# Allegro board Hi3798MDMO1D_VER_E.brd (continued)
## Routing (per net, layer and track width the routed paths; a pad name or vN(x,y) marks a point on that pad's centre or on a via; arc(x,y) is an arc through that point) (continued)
DDR_ADDR3: length 127.3
  TOP w0.127: U21.K2 37.09,12.08 38.2,12.08 39.04,11.24 39.04,8.37 v2(39.11,8.3) ; U3.K2 35.31,46.38 35.31,45.56 34.31,44.56 31.75,44.56 v2(31.57,44.38) ; U6.K2 35.31,31.75 35.31,30.79 34.44,29.93 32.2,29.93 30.8,28.53 v2(30.8,27.96) ; U20.K2 52.22,12.08 53.15,12.08 54.07,11.17 54.07,8.48 v2(54.2,8.35) 54.72,7.83 54.72,7.34 56.3,5.76 57.13,5.76 63.31,11.93 63.31,21.85 60.51,24.65 60.51,27.68 59.92,28.27 U1.AC14
  BOTTOM w0.127: RN6.2 29.95,47.17 30.56,46.55 30.56,46.35 31.57,45.34 v2(31.57,44.38) 31.57,43.75 31.06,43.24 31.06,42.12 30.16,41.22 30.16,32.18 31.53,30.81 31.53,28.44 31.04,27.96 v2(30.8,27.96) 30.8,27.96 30.7,27.96 25.82,23.07 25.82,12.98 31.59,7.21 37.58,7.21 38.67,8.3 v2(39.11,8.3) 39.52,7.89 41.14,7.89 41.64,7.39 47.3,7.39 47.66,7.03 51.44,7.03 52.76,8.35 v2(54.2,8.35)
DDR_ADDR4: length 105
  TOP w0.127: v2(41.88,11.29) U21.L8 ; U6.L8 34.92,27.36 v2(34.52,26.96) ; U1.W12 v2(57.92,31.8) ; U20.L8 v2(57.01,12.09) ; U3.L8 34.92,41.99 v2(34.52,41.59)
  BOTTOM w0.127: RN4.3 32.11,48.28 34.55,45.85 34.55,42.96 34.92,42.59 34.92,41.99 v2(34.52,41.59) 34.52,41.37 33.96,40.81 33.51,40.81 32.75,40.05 32.75,39.62 32.88,39.49 32.88,34.66 33.72,33.82 33.72,33.42 34.55,32.59 34.55,28.35 34.91,27.99 34.91,27.6 34.52,27.2 v2(34.52,26.96) 34.52,26.52 33.71,25.71 33.71,25.6 33.43,25.32 32.01,25.32 28.48,21.79 28.48,14.09 32.67,9.9 34.71,9.9 34.91,9.7 35.79,9.7 37.39,11.29 40.46,11.29 40.85,11.68 41.48,11.68 v2(41.88,11.29) 42.3,11.29 43.09,10.49 43.55,10.49 43.91,10.13 49.3,10.13 49.77,9.67 50.65,9.67 52.3,11.32 55.63,11.32 56.01,11.7 56.62,11.7 v2(57.01,12.09) 57.82,11.28 59.54,11.28 60.6,12.35 60.6,20.15 57.55,23.2 57.55,29.02 57.44,29.13 57.44,30.53 57.92,31.01 v2(57.92,31.8)
DDR_ADDR5: length 132.1
  TOP w0.127: v1(39.91,6.9) 39.3,6.9 38.41,7.79 38.41,10.72 38.2,10.93 38.2,10.94 37.82,11.32 37.29,11.32 36.91,11.69 U21.L2 ; U6.L2 34.92,31.92 34.55,31.55 34.55,31.02 34.01,30.49 32.12,30.49 32.11,30.48 31.57,30.48 30.54,29.44 v2(30.54,28.92) ; v1(55.43,5.79) 55.1,6.12 54.52,6.12 53.81,6.83 53.81,7.56 53.51,7.86 53.51,10.73 52.92,11.32 52.42,11.32 52.05,11.69 U20.L2 ; U1.Y15 v2(61.12,31) ; v2(30.61,44.43) 31.34,45.17 34.06,45.17 34.55,45.65 34.55,46.14 34.92,46.51 U3.L2
  BOTTOM w0.127: v2(61.12,31) 61.96,30.16 61.96,28.24 62.3,27.9 62.3,24.2 64.44,22.06 64.44,10.79 59.43,5.79 v1(55.43,5.79) 55.33,5.89 54.03,5.89 53.17,5.02 45.6,5.02 44.04,6.59 40.41,6.59 40.09,6.9 v1(39.91,6.9) 38.64,6.9 38.18,6.45 31.27,6.45 25.05,12.67 25.05,23.41 30.54,28.9 v2(30.54,28.92) 30.54,29.36 30.54,29.37 30.54,30.17 29.4,31.32 29.4,41.68 30.29,42.57 30.29,44.11 v2(30.61,44.43) 30.61,45.42 29.87,46.16 RN6.4
DDR_ADDR6: length 104.3
  TOP w0.127: v2(33.72,26.96) 34.12,27.36 U6.M8 ; v2(41.88,10.49) U21.M8 ; v2(33.72,41.59) 34.12,41.99 U3.M8 ; U20.M8 v2(57.01,10.49) 59.3,10.49 61.76,12.95 61.76,21.25 58.89,24.12 58.89,26.41 56.8,28.49 56.8,29.38 57.08,29.66 57.08,30.24 U1.AA10
  BOTTOM w0.127: v2(57.01,10.49) 52.46,10.49 50.99,9.01 49.06,9.01 48.79,9.28 42.78,9.28 42.27,9.79 42.27,10.1 v2(41.88,10.49) 37.78,10.49 36.41,9.11 32.38,9.11 27.72,13.77 27.72,22.15 31.55,25.98 32.38,25.98 32.78,26.39 33.14,26.39 v2(33.72,26.96) 33.72,31.95 32.06,33.6 32.06,40.18 33.47,41.59 v2(33.72,41.59) 33.72,45.61 31.4,47.93 31.4,49.07 30.36,50.11 RN3.1
DDR_ADDR7: length 116.1
  TOP w0.127: RN2.2 33.64,50.14 33.84,49.93 33.84,49.31 33.72,49.19 33.72,47.51 34.12,47.11 U3.M2 34.12,46.6 33.74,46.22 33.74,45.81 33.57,45.65 30.75,45.65 29.78,44.67 29.78,44.01 30.36,43.43 30.36,43.12 30.79,42.69 30.79,36.98 33.72,34.05 33.72,32.86 34.12,32.46 U6.M2 34.12,31.97 33.71,31.56 33.71,31.19 33.54,31.02 31.11,31.02 29.75,29.66 29.75,24.58 31.07,23.26 31.07,15.49 33.82,12.75 33.82,11.98 34.53,11.27 34.53,10.97 35.01,10.49 36.06,10.49 36.46,10.89 U21.M2 36.89,10.89 37.35,10.43 37.62,10.43 37.83,10.22 37.83,9.9 37.63,9.7 37.63,7.44 38.92,6.14 42.71,6.14 44.03,4.82 47.35,4.82 48.68,6.14 48.68,8.17 49.79,9.29 49.79,10.21 50.08,10.5 51.15,10.5 51.54,10.89 U20.M2 51.98,10.89 52.38,10.49 52.79,10.49 52.99,10.28 52.99,9.77 52.74,9.52 52.74,7.59 53.09,7.23 53.09,6.37 54.59,4.87 56.8,4.87 63.69,11.76 63.69,22.02 60.92,24.79 60.92,27.94 60.36,28.49 60.36,29.36 U1.AB14
DDR_ADDR8: length 103.7
  TOP w0.127: v2(32.92,41.59) U3.N8 ; v2(32.92,26.96) U6.N8 ; U20.N8 v2(57.01,9.69) 59.18,9.69 62.14,12.64 62.14,21.41 59.32,24.22 59.32,26.61 57.16,28.77 57.16,29.23 57.52,29.59 U1.AB11 ; v2(41.88,9.69) U21.N8
  BOTTOM w0.127: v2(57.01,9.69) 56.62,10.08 52.54,10.08 51.14,8.68 48.68,8.68 48.46,8.9 42.67,8.9 v2(41.88,9.69) 41.48,10.08 38.06,10.08 36.71,8.73 32.22,8.73 27.34,13.61 27.34,22.33 31.32,26.31 32.14,26.31 32.79,26.96 v2(32.92,26.96) 33.31,27.36 33.31,31.64 31.68,33.27 31.68,40.41 32.87,41.59 v2(32.92,41.59) 33.31,41.99 33.31,45.51 31.02,47.8 31.02,48.81 30.23,49.6 RN3.2
DDR_ADDR9: length 118.4
  TOP w0.127: U1.Y16 v2(61.92,31.8) ; RN2.3 34.15,50.21 34.51,49.85 34.51,46.56 34.12,46.17 U3.M3 34.12,45.74 33.8,45.42 31.01,45.42 30.16,44.57 30.16,44.12 30.74,43.53 30.74,43.28 31.2,42.82 31.2,37.26 34.52,33.93 34.52,31.97 34.12,31.56 U6.M3 34.12,31.11 33.77,30.76 31.34,30.76 30.13,29.56 30.13,24.81 31.45,23.49 31.45,17.06 33.42,15.1 33.42,13.7 34.17,12.95 34.17,12.21 35.09,11.3 36.93,11.3 37.33,10.89 U21.M3 37.69,10.89 38.11,10.47 38.11,9.67 38.01,9.57 38.01,7.62 39.15,6.48 43.01,6.48 44.26,5.23 47.13,5.23 48.28,6.38 48.28,8.41 49.36,9.5 49.36,10.64 50.02,11.3 52.03,11.3 52.44,10.89 U20.M3 52.84,10.89 53.25,10.48 53.25,9.6 53.12,9.47 53.12,7.72 53.42,7.41 53.42,6.62 54.62,5.43 v1(54.69,5.43)
  BOTTOM w0.127: v1(54.69,5.43) 54.82,5.3 59.49,5.3 64.82,10.63 64.82,22.22 62.68,24.36 62.68,28.31 62.31,28.67 62.31,31.4 v2(61.92,31.8)
DDR_ADDR10: length 93.6
  TOP w0.127: v2(36.89,28.67) 37.32,28.24 U6.H7 ; v2(55.36,13.56) 55.36,13.63 U20.H7 ; U3.H7 37.32,42.9 36.99,43.23 v2(36.84,43.23) ; 55.12,31.4 55.12,31.38 54.72,30.98 v2(54.72,29.4) ; U21.H7 40.6,14.09 v2(40.24,13.73)
  BOTTOM w0.127: v2(54.72,29.4) 54.72,23.59 56.14,22.17 56.14,19.76 57.51,18.39 57.51,16.35 58.28,15.58 58.28,14.3 58.08,14.09 57.79,14.09 57.57,13.86 55.66,13.86 v2(55.36,13.56) 55.03,13.24 52.71,13.24 52.26,13.68 50.2,13.68 50.02,13.51 46.39,13.51 45.81,14.08 40.59,14.08 v2(40.24,13.73) 40.24,13.51 39.97,13.24 35.9,13.24 35.45,13.68 32.66,13.68 30.41,15.93 30.41,20.96 32.36,22.91 35.94,22.91 37.31,24.28 37.31,28.25 v2(36.89,28.67) 36.53,29.03 36.53,32.34 37.31,33.12 37.31,33.94 36.91,34.34 36.91,41 37.04,41.12 37.04,42.39 37.14,42.48 37.14,42.93 v2(36.84,43.23) 36.53,43.54 36.53,47.24 36.13,47.65 36.13,47.99 36.12,47.99 36.12,48.32 36.13,48.33 36.13,49.6 36.13,49.61 36.13,50.42 35.51,51.05 RN7.1
DDR_ADDR11: length 103.3
  TOP w0.127: v2(41.08,11.29) U21.M7 ; v2(34.52,27.76) U6.M7 ; U1.AB9 56.42,29.3 56.42,28.24 58.46,26.21 58.46,24.01 61.38,21.09 61.38,13.23 59.44,11.29 v2(56.21,11.29) U20.M7 ; v2(34.52,42.39) U3.M7
  BOTTOM w0.127: RN4.4 31.61,49.5 31.76,49.35 31.76,48.08 34.16,45.67 34.16,42.74 v2(34.52,42.39) 34.12,42 34.12,41.44 33.77,41.09 33.38,41.09 32.42,40.13 32.42,33.9 34.12,32.2 34.12,28.16 v2(34.52,27.76) 34.12,27.37 34.12,26.81 33.47,26.16 33.13,26.16 32.57,25.6 31.73,25.6 28.1,21.97 28.1,13.93 32.54,9.5 33.72,9.5 33.75,9.47 36.18,9.47 37.6,10.89 40.67,10.89 v2(41.08,11.29) 41.48,10.88 42.04,10.88 42.5,10.42 42.5,10.16 42.99,9.67 49.06,9.67 49.39,9.34 50.81,9.34 52.4,10.94 55.86,10.94 v2(56.21,11.29)
DDR_ADDR12: length 98.3
  TOP w0.127: v2(36.12,27.76) U6.K7 ; v2(56.21,12.89) U20.K7 ; v2(41.08,12.89) U21.K7 ; v2(36.12,42.39) U3.K7 ; U1.Y10 v2(56.32,31)
  BOTTOM w0.127: RN7.4 33.99,50.65 34.52,50.11 34.52,47.65 35.69,46.49 35.69,42.97 36.12,42.54 36.12,42.39 v2(36.12,42.39) 36.52,41.99 36.52,41.33 36.1,40.91 35.75,40.91 35.32,40.49 35.32,37.53 36.12,36.73 36.12,33.33 35.69,32.9 35.69,28.4 36.12,27.97 v2(36.12,27.76) 36.51,27.37 36.51,24.58 35.6,23.67 32.01,23.67 29.64,21.31 29.64,15.03 32.82,11.86 34.81,11.86 35.04,12.09 35.4,12.09 35.79,12.49 40.49,12.49 40.89,12.89 v2(41.08,12.89) 41.54,13.35 42.14,13.35 42.6,12.88 45.74,12.88 46.52,12.11 50.16,12.11 50.18,12.1 50.5,12.1 50.52,12.11 50.61,12.11 50.96,12.46 55.58,12.46 56.01,12.89 v2(56.21,12.89) 56.61,13.28 57.36,13.28 57.69,12.95 58.2,12.95 59.83,14.58 59.83,19.72 56.71,22.84 56.71,30.6 v2(56.32,31)
DDR_ADDR13: length 118.8
  TOP w0.127: RN2.1 33.13,50.22 32.89,49.99 32.89,47.48 33.12,47.25 33.48,47.25 33.66,47.07 33.66,46.57 33.32,46.22 U3.N3 30.54,45.99 29.37,44.83 29.37,44.2 29.37,44.2 29.37,43.88 29.37,43.85 29.86,43.36 29.86,43.36 29.9,43.31 29.9,43.04 30.41,42.53 30.41,36.67 32.81,34.28 32.81,32.99 33.17,32.62 33.45,32.62 33.66,32.41 33.66,31.94 33.32,31.59 U6.N3 30.71,31.36 29.37,30.02 29.37,24.3 30.69,22.98 30.69,15.31 33.45,12.56 33.45,11.84 34.07,11.22 34.07,10.66 35.04,9.7 36.07,9.7 36.28,9.9 36.28,10.18 36.53,10.43 36.9,10.43 37.24,10.09 U21.N3 37.25,9.86 37.25,7.18 38.67,5.76 42.52,5.76 43.85,4.43 47.73,4.43 49.18,5.89 49.18,7.72 51.42,9.96 51.42,10.26 51.59,10.43 52.04,10.43 52.38,10.09 U20.N3 52.61,9.83 52.36,9.57 52.36,7.41 52.69,7.08 52.69,6.22 54.42,4.49 57.01,4.49 64.09,11.58 64.09,22.17 61.32,24.94 61.32,27.88 61.63,28.19 61.63,29.26 61.91,29.54 61.91,30.21 U1.AA16
DDR_ADDR14: length 103
  TOP w0.127: v2(56.21,9.69) U20.N7 ; v2(32.92,27.76) U6.N7 ; v2(57.92,30.2) 57.52,30.6 U1.AA11 ; v2(41.08,9.69) U21.N7 ; v2(32.92,42.39) U3.N7
  BOTTOM w0.127: RN3.3 30.11,49.09 30.64,48.56 30.64,47.8 31.4,47.04 31.4,46.87 32.92,45.36 v2(32.92,42.39) 32.92,42.28 31.3,40.66 31.3,32.86 32.92,31.25 v2(32.92,27.76) 31.79,26.64 31.09,26.64 26.96,22.51 26.96,13.46 32.06,8.35 36.94,8.35 38.28,9.69 v2(41.08,9.69) 41.14,9.69 42.33,8.5 48.22,8.5 48.42,8.3 51.27,8.3 52.65,9.69 v2(56.21,9.69) 56.61,9.3 58.09,9.3 60.99,12.2 60.99,20.48 57.96,23.51 57.96,28.8 58.33,29.17 58.33,29.79 v2(57.92,30.2)
DDR_ADDR15: length 96.2
  TOP w0.127: v2(36.12,43.19) U3.J7 ; v2(40.28,12.89) U21.J7 ; U1.W10 v2(56.32,31.8) ; v2(36.12,28.56) U6.J7 ; v2(55.41,12.89) U20.J7
  BOTTOM w0.127: v2(56.32,31.8) 55.91,31.39 55.91,31.16 55.91,30.42 55.38,29.89 55.38,23.57 59.45,19.5 59.45,14.96 58.22,13.73 57.87,13.73 57.67,13.53 56.06,13.53 v2(55.41,12.89) 55.41,12.88 50.14,12.88 49.93,13.1 46.14,13.1 45.77,13.46 43.72,13.46 43.47,13.71 41.13,13.71 40.31,12.89 v2(40.28,12.89) 40.27,12.9 34.95,12.9 34.64,13.21 32.59,13.21 30.03,15.78 30.03,21.11 32.2,23.29 35.76,23.29 36.74,24.27 36.74,27.94 v2(36.12,28.56) 36.07,28.61 36.07,32.5 36.92,33.35 36.92,33.75 36.48,34.18 36.48,39.72 36.12,40.08 36.12,40.53 36.79,41.19 36.79,42.52 v2(36.12,43.19) 36.07,43.24 36.07,46.87 35.31,47.62 35.31,48.38 34.91,48.79 34.91,50.54 35,50.64 RN7.2
DDR_BA0: length 115.6
  TOP w0.127: RN2.4 34.65,50.36 35.31,49.7 35.31,47.37 35.47,47.21 35.9,47.21 36.32,46.79 U3.J2 36.07,46.34 36.07,45.35 34.75,44.03 32.45,44.03 31.96,43.54 31.96,42.9 31.58,42.52 31.58,37.64 35.31,33.91 35.31,32.82 35.54,32.58 35.9,32.58 36.32,32.16 U6.J2 36.52,31.98 36.07,31.53 36.07,30.67 34.75,29.35 32.44,29.35 31.78,28.7 31.78,26.87 31.4,26.49 31.4,24.25 31.83,23.82 31.83,17.39 33.82,15.41 33.82,13.89 34.5,13.2 34.5,12.57 34.97,12.1 36.04,12.1 36.3,12.36 36.3,12.66 36.68,13.04 U21.J2 36.87,13.29 37.31,12.85 37.31,12.84 38.45,12.84 39.66,11.64 39.66,9 39.93,8.73 41.39,8.73 44.46,5.66 46.87,5.66 47.81,6.6 47.81,8.71 48.8,9.7 48.8,10.84 50.04,12.08 51.19,12.08 51.42,12.31 51.42,12.65 51.81,13.04 U20.J2 52.1,13.29 52.55,12.84 53.35,12.84 54.62,11.57 54.62,9.18 55.82,7.98 55.82,7.57 v1(56.78,6.61) ; U1.AC15 v2(61.12,28.6)
  BOTTOM w0.127: v1(56.78,6.61) 59.18,6.61 63.67,11.11 63.67,21.75 60.98,24.44 60.98,28.46 v2(61.12,28.6)
DDR_BA1: length 100.5
  TOP w0.127: v2(35.32,26.96) 35.72,27.36 U6.K8 ; v2(41.88,12.89) U21.K8 ; U20.K8 v2(57.01,12.89) 59.08,12.89 59.1,12.87 60.28,12.87 60.99,13.58 60.99,20.93 58.02,23.9 58.02,25.77 55.47,28.32 55.47,28.7 55.53,28.77 55.53,30.21 U1.AA9 ; v2(36.12,41.59) U3.K8
  BOTTOM w0.127: RN4.1 33.13,50.44 32.9,50.21 32.9,49.17 33.71,48.36 33.71,47.7 35.31,46.1 35.31,43 35.72,42.6 35.72,42.09 36.12,41.69 v2(36.12,41.59) 35.74,41.22 35.29,41.22 34.52,40.45 34.52,39.98 34.95,39.56 34.95,34.14 35.32,33.77 35.32,28.39 35.71,28 35.71,27.36 v2(35.32,26.96) 35.32,25.16 34.21,24.05 31.85,24.05 29.26,21.46 29.26,14.86 32.72,11.4 34.86,11.4 34.96,11.3 35.46,11.3 36.26,12.09 40.47,12.09 40.86,12.48 41.47,12.48 v2(41.88,12.89) 42.68,12.08 43.4,12.08 43.76,11.73 49.67,11.73 50.11,11.29 50.65,11.29 51.44,12.08 55.63,12.08 56.03,12.48 56.38,12.48 56.79,12.89 v2(57.01,12.89)
DDR_BA2: length 125.2
  TOP w0.127: v2(55.22,9.18) 54.9,9.5 54.9,11.8 53.47,13.24 52.67,13.24 U20.J3 ; U3.J3 36.52,45.29 34.93,43.71 32.73,43.71 v2(32.41,43.39) ; v2(32.41,28.76) 32.73,29.07 35,29.07 36.52,30.59 U6.J3 ; U1.Y12 v2(58.72,31.8) ; v2(40.08,9.18) 39.96,9.3 39.96,11.84 38.51,13.29 U21.J3
  BOTTOM w0.127: RN3.4 30.06,48.59 30.26,48.38 30.26,47.8 31.15,46.91 31.15,46.71 32.41,45.44 v2(32.41,43.39) 32.41,42.33 30.92,40.84 30.92,32.56 32.41,31.07 v2(32.41,28.76) 32.41,28 31.35,26.94 30.84,26.94 26.58,22.68 26.58,13.3 31.9,7.97 37.09,7.97 38.31,9.18 v2(40.08,9.18) 41.04,9.18 42.1,8.12 47.84,8.12 48.17,7.79 51.27,7.79 52.66,9.18 v2(55.22,9.18) 55.4,9 58.34,9 61.38,12.04 61.38,20.79 58.41,23.75 58.41,28.65 58.71,28.95 58.71,30.27 58.33,30.65 58.33,31.4 v2(58.72,31.8)
DDR_CASN: length 118.6
  TOP w0.127: v2(38.44,45.54) 38.12,45.87 U3.G3 ; U6.G3 v2(38.52,30.96) ; U21.G3 v2(37.88,15.29) ; v2(46.77,6.98) 46.77,9.32 47.46,10 47.46,11.35 49.84,13.73 51.23,13.73 51.44,13.94 51.44,14.27 51.69,14.52 52.1,14.52 52.47,14.89 U20.G3 v2(53.01,15.29) ; U1.Y14 v2(59.52,31)
  BOTTOM w0.127: RN5.2 37.39,50.85 37.64,50.61 37.66,50.61 38.1,50.17 38.1,50.15 38.12,50.12 38.12,47.89 37.63,47.39 37.63,46.66 38.44,45.84 38.44,45.54 v2(38.44,45.54) 38.44,43.95 38.85,43.55 38.85,38.96 38.95,38.86 38.95,33.37 38.67,33.09 38.49,33.09 38.1,32.7 38.1,31.38 v2(38.52,30.96) 38.59,30.89 38.59,28.42 38.74,28.26 38.74,26.95 39.01,26.68 39.01,24.36 36.41,21.76 32.93,21.76 31.55,20.39 31.55,16.77 32.62,15.69 32.67,15.69 35.7,15.69 35.87,15.51 35.87,15.01 35.98,14.9 37.48,14.9 v2(37.88,15.29) 39.15,15.29 39.91,16.05 46.39,16.05 46.64,15.79 48.8,15.79 49.18,15.41 49.79,15.41 50.12,15.74 50.63,15.74 51.48,14.9 52.6,14.9 53,15.29 v2(53.01,15.29) ; v2(59.52,31) 59.98,30.54 59.98,28.34 59.68,28.04 59.68,24.12 62.53,21.28 62.53,11.58 58.77,7.82 55.53,7.82 55.22,7.51 53.22,7.51 52.31,6.6 47.15,6.6 v2(46.77,6.98)
DDR_CKE: length 94.2
  TOP w0.127: U21.G9 42.62,14.89 v2(42.85,15.12) ; U3.G9 38.15,41.16 v2(38.15,40.56) ; U6.G9 38.12,26.13 v2(38.36,25.88) ; U1.W9 v2(55.52,31.8) ; v2(57.81,14.49) U20.G9
  BOTTOM w0.127: RN5.4 36.37,50.73 36.5,50.6 36.5,50.6 36.56,50.54 36.56,48.81 36.91,48.46 36.91,46.38 37.63,45.66 37.63,45.31 37.8,45.13 37.8,43.83 38.15,43.48 v2(38.15,40.56) 38.13,40.56 38.13,33.91 38.1,33.88 38.1,33.41 37.5,32.8 37.5,30.93 38.05,30.39 38.05,28 38.13,27.91 38.13,26.79 38.36,26.56 v2(38.36,25.88) 38.36,24.79 36.1,22.53 32.52,22.53 30.79,20.8 30.79,16.09 32.79,14.09 39.09,14.09 40.13,15.12 v2(42.85,15.12) 45.41,15.12 46.68,13.85 49.98,13.85 50.2,14.06 53.17,14.06 54.09,14.98 56.35,14.98 56.61,14.71 56.61,14.33 56.85,14.09 57.42,14.09 v2(57.81,14.49) 57.81,15.42 57.11,16.12 57.11,17.75 R38.2 56.35,18.87 55.74,19.48 55.74,21.99 54.3,23.43 54.3,29.55 55.1,30.35 55.1,31.38 v2(55.52,31.8)
DDR_CLK1N: length 88.1
  TOP w0.114: v1(39.29,29.57) 39.29,29.34 38.12,28.17 U6.G7 ; U3.G7 39.29,43.96 v1(39.29,44.05) ; v1(54.48,15.88) 54.48,15.72 55.31,14.89 U20.G7 56,14.89 56.4,15.29 57.62,15.29 57.87,15.54 58.28,15.54 60.11,17.37 60.11,20.46 55.46,25.11 55.46,25.9 R37.1 ; U21.G7 39.22,16.34 v1(39.09,16.34)
  BOTTOM w0.114: v1(54.48,15.88) 54.21,16.15 51.8,16.15 51.35,16.59 39.34,16.59 v1(39.09,16.34) 38.84,16.59 38.58,16.59 38.22,16.24 36.73,16.24 36.48,16.48 33.18,16.48 32.3,17.36 32.3,19.92 33.38,21 37.17,21 40.92,24.75 40.92,26.5 39.93,27.48 39.93,28.8 39.7,29.04 39.6,29.13 39.6,29.26 v1(39.29,29.57) 39.39,29.67 39.39,32.06 39.77,32.45 39.77,39.12 39.45,39.45 39.45,43.89 v1(39.29,44.05) 39.44,44.2 39.44,49.06 38.91,49.59 38.91,50.43 38.79,50.55 RN1.4
DDR_CLK1P: length 87.5
  TOP w0.114: v1(39.09,17.05) 40.45,15.69 U21.F7 ; R36.1 55.03,26.18 55.19,26.02 55.19,25 59.84,20.35 59.84,17.48 58.17,15.81 57.88,15.81 57.6,16.09 56.21,16.09 U20.F7 55.38,16.13 54.99,16.13 v1(54.5,16.62) ; v1(40.01,29.57) 39.87,29.57 38.92,28.62 U6.F7 ; U3.F7 38.92,43.01 39.95,44.05 v1(40.01,44.05)
  BOTTOM w0.114: v1(54.5,16.62) 54.3,16.42 51.91,16.42 51.47,16.86 39.28,16.86 v1(39.09,17.05) 38.89,16.86 38.47,16.86 38.11,16.5 36.84,16.5 36.59,16.75 33.3,16.75 32.57,17.47 32.57,19.81 33.49,20.73 37.28,20.73 41.18,24.64 41.18,26.64 40.2,27.62 40.2,28.91 39.96,29.15 39.96,29.55 39.99,29.57 ; RN1.3 39.3,50.48 39.18,50.36 39.18,49.7 39.71,49.17 39.71,44.36 v1(40.01,44.05) 39.72,43.75 39.72,39.56 40.04,39.23 40.04,32.34 39.65,31.95 39.65,29.88 39.96,29.57 39.99,29.57 ; 39.99,29.57 v1(40.01,29.57)
DDR_CSN: length 102.2
  TOP w0.127: U20.H2 52.13,14.09 52.53,14.49 v2(53.01,14.49) 53.26,14.49 55.47,12.27 55.47,9.86 56.04,9.3 59.35,9.3 62.52,12.47 62.52,21.56 59.72,24.36 59.72,27.05 58.66,28.11 58.66,28.66 U1.AC12 ; v2(38.36,14.57) 38.29,14.5 37.09,14.5 U21.H2 36.36,14.09 36,13.73 35.22,13.73 34.71,14.24 34.71,15.79 32.67,17.83 32.67,26.46 32.5,26.64 32.5,27.9 33.12,28.52 35.42,28.52 36.61,29.71 36.97,29.71 37.72,30.46 37.72,31.6 37.32,32 U6.H2 37.32,32.41 36.96,32.77 36.96,34.59 36.05,35.5 36.05,36.42 32.39,40.08 32.39,42.42 33.1,43.14 35.25,43.14 36.61,44.5 37.04,44.5 37.72,45.17 37.72,46.08 37.32,46.48 U3.H2 37.32,47.02 36.91,47.42 36.91,48.48 36.54,48.86 36.54,49.58 36.99,50.03 36.99,50.44 37.45,50.9 37.45,51.28 R33.1
  BOTTOM w0.127: v2(38.36,14.57) 39.2,14.57 40.14,15.51 45.62,15.51 46.26,14.87 50.71,14.87 51.1,14.49 v2(53.01,14.49)
DDR_DM0: length 14.3
  TOP w0.127: U3.B7 41.72,42.39 v2(41.72,40.79) ; U1.K4 v2(51.52,39)
  BOTTOM w0.127: v2(51.52,39) 51.13,39.39 50.53,39.39 49.67,38.53 47.15,38.53 44.48,41.19 42.12,41.19 v2(41.72,40.79)
DDR_DM1: length 17.4
  TOP w0.127: 52.72,38.6 v2(52.32,39) ; v2(44.36,30.53) 42.12,28.29 U6.B7
  BOTTOM w0.127: v2(44.36,30.53) 44.36,34.08 48.47,38.2 50.83,38.2 51.24,38.6 51.93,38.6 v2(52.32,39)
DDR_DM2: length 17.4
  TOP w0.127: U21.B7 41.03,19.24 41.03,19.73 41.33,20.03 42.42,20.03 42.43,20.02 v2(44.19,20.02) ; U1.AA1 v2(49.12,30.2)
  BOTTOM w0.127: v2(44.19,20.02) 44.19,20.46 49.21,25.47 49.21,27.83 49.53,28.15 49.53,29.79 v2(49.12,30.2)
DDR_DM3: length 16.6
  TOP w0.127: U1.Y2 49.86,30.94 49.11,30.94 48.68,30.5 48.68,28.34 50.91,26.11 50.91,23.95 55.24,19.62 55.24,19.46 U20.B7
DDR_DQ0: length 12.2
  TOP w0.127: U1.H4 51.52,40.6 47.51,40.6 U3.B3
DDR_DQ1: length 12.9
  TOP w0.127: U3.C7 v2(41.72,43.19) ; 52.72,41 v2(52.32,41.4)
  BOTTOM w0.127: v2(41.72,43.19) 42.6,43.19 42.73,43.33 44.89,43.33 47.22,41 51.92,41 v2(52.32,41.4)
DDR_DQ2: length 11.1
  TOP w0.127: U1.H1 47.65,41 43.34,45.31 43.34,46.1 43.05,46.39 41.99,46.39 41.58,46.79 U3.C2
DDR_DQ3: length 13.6
  TOP w0.127: v2(40.92,42.39) U3.C8 ; U1.J4 v2(52.32,40.6)
  BOTTOM w0.127: v2(40.92,42.39) 41.29,42.77 44.79,42.77 46.96,40.6 v2(52.32,40.6)
DDR_DQ4: length 13.8
  TOP w0.127: U3.E3 40.09,46.36 41.52,46.36 41.73,46.15 41.73,45.82 47.46,40.1 49.18,40.1 49.49,39.8 49.92,39.8 U1.K2
DDR_DQ5: length 13.8
  TOP w0.127: U3.E8 v2(40.12,41.59) ; 51.12,40.2 v2(50.72,39.8)
  BOTTOM w0.127: v2(40.12,41.59) 40.51,41.2 41.14,41.2 41.94,42.01 44.31,42.01 47.33,38.98 49.63,38.98 50.45,39.8 v2(50.72,39.8)
DDR_DQ6: length 13.9
  TOP w0.127: U1.H2 v2(50.72,41.4) ; U3.D2 v2(40.92,47.19)
  BOTTOM w0.127: v2(50.72,41.4) 47.58,41.4 45.2,43.79 43.34,43.79 40.92,46.21 v2(40.92,47.19)
DDR_DQ7: length 15.1
  TOP w0.127: U3.E7 v2(40.12,42.39) ; v2(52.32,39.8) 52.72,40.2
  BOTTOM w0.127: v2(52.32,39.8) 51.93,40.19 50.39,40.19 50,39.8 47.15,39.8 44.56,42.39 41.61,42.39 41.22,42 40.51,42 v2(40.12,42.39)
DDR_DQ8: length 16.1
  TOP w0.127: U6.B3 v2(42.52,30.96) ; U1.M4 v2(51.52,37.4)
  BOTTOM w0.127: v2(42.52,30.96) 42.52,30.59 43.41,29.7 44.74,29.7 45.31,30.27 45.31,33.77 48.93,37.38 51.51,37.38 v2(51.52,37.4)
DDR_DQ9: length 13
  TOP w0.127: U6.C7 44.56,31.41 44.56,33.29 48.26,37 U1.N1
DDR_DQ10: length 17.9
  TOP w0.127: U6.C2 v2(41.72,31.76) ; U1.N4 v2(51.52,36.6)
  BOTTOM w0.127: v2(51.52,36.6) 51.12,37 49.18,37 45.7,33.52 45.7,30.12 44.84,29.26 43.26,29.26 42.12,30.4 42.12,31.36 v2(41.72,31.76)
DDR_DQ11: length 15.2
  TOP w0.127: U1.P2 49.95,36.57 49.38,36.57 49.24,36.7 48.55,36.7 45,33.15 45,29.47 43.3,27.77 41.72,27.77 U6.C8
DDR_DQ12: length 18.8
  TOP w0.127: v2(40.13,30.36) 39.72,30.77 U6.E3 ; U1.P4 v2(51.52,35.8)
  BOTTOM w0.127: v2(40.13,30.36) 41.55,30.36 43.04,28.88 45.07,28.88 46.11,29.92 46.11,31.14 46.12,31.15 46.12,33.07 48.78,35.73 49.11,35.73 49.56,36.19 51.13,36.19 v2(51.52,35.8)
DDR_DQ13: length 20.1
  TOP w0.127: U6.E8 39.72,27.09 40.12,26.69 40.12,25.78 40.72,25.17 42.99,25.17 45.76,27.94 45.76,32.69 48.12,35.05 49.29,35.05 49.37,34.97 50.48,34.97 50.9,35.4 U1.R3 51.12,35.4
DDR_DQ14: length 19.3
  TOP w0.127: U6.D2 v2(40.92,31.76) ; 52.72,37.8 v2(52.32,38.2)
  BOTTOM w0.127: v2(40.92,31.76) 41.34,32.18 42.07,32.18 43.09,31.16 43.09,30.65 43.65,30.09 44.56,30.09 44.87,30.4 44.87,33.96 48.7,37.79 51.91,37.79 v2(52.32,38.2)
DDR_DQ15: length 20.2
  TOP w0.127: U6.E7 40.17,27.71 40.17,27.11 40.32,26.97 40.7,26.97 40.9,26.77 40.9,26.39 41.63,25.66 42.87,25.66 45.38,28.17 45.38,32.95 48.12,35.69 49.36,35.69 49.5,35.82 50.75,35.82 51.12,36.2
DDR_DQ16: length 21.5
  TOP w0.127: U21.B3 37.98,19.4 37.98,20.19 41.97,24.18 43.37,24.18 46.64,27.45 46.64,32.3 48.14,33.8 U1.U1
DDR_DQ17: length 23.5
  TOP w0.127: 51.12,34.6 v2(51.52,34.2) ; U21.C7 v2(40.28,18.49)
  BOTTOM w0.127: v2(40.28,18.49) 40.28,20.65 41.84,22.22 42.91,22.22 47.35,26.66 47.35,31.81 50.12,34.59 50.56,34.59 50.56,34.59 50.88,34.59 50.89,34.59 50.99,34.59 51.38,34.2 v2(51.52,34.2)
DDR_DQ18: length 24.1
  TOP w0.127: U21.C2 37.07,18.48 37.07,19.91 41.76,24.61 43.11,24.61 46.26,27.76 46.26,32.56 47.87,34.16 49.32,34.16 49.37,34.21 49.93,34.21 U1.T2
DDR_DQ19: length 21.9
  TOP w0.127: U21.C8 v2(41.07,18.5) ; 51.12,33.8 v2(51.52,33.4)
  BOTTOM w0.127: v2(51.52,33.4) 50.13,33.4 48.2,31.47 48.2,25.99 43.42,21.2 42.15,21.2 41.07,20.13 v2(41.07,18.5)
DDR_DQ20: length 27.5
  TOP w0.127: 52.72,34.6 v2(52.32,35) ; U21.E3 v2(37.88,16.89)
  BOTTOM w0.127: v2(52.32,35) 51.93,34.6 51.33,34.6 50.96,34.97 49.95,34.97 46.95,31.98 46.95,27.02 42.66,22.73 41.64,22.73 38.82,19.91 38.82,18.61 37.88,17.67 v2(37.88,16.89)
DDR_DQ21: length 23.2
  TOP w0.127: U21.E8 41.89,16.91 42.39,16.91 43.41,17.93 43.41,18.19 v2(43.73,18.51) ; U1.U4 v2(52.32,33.4)
  BOTTOM w0.127: v2(43.73,18.51) 43.77,18.55 43.77,20.8 48.66,25.69 48.66,30.39 49.44,31.16 49.44,32.1 50.34,33 51.93,33 v2(52.32,33.4)
DDR_DQ22: length 28.1
  TOP w0.127: 52.72,35.4 v2(52.32,35.8) ; U21.D2 v2(37.08,17.69)
  BOTTOM w0.127: v2(52.32,35.8) 51.91,35.39 51.35,35.39 50.92,35.83 49.61,35.83 46.52,32.74 46.52,27.22 42.52,23.23 41.45,23.23 37.96,19.73 37.96,19.13 37.49,18.66 37.49,18.1 v2(37.08,17.69)
DDR_DQ23: length 25.3
  TOP w0.127: U1.T4 v2(52.32,34.2) ; U21.E7 40.68,16.71 41.08,17.11 v2(41.08,17.69)
  BOTTOM w0.127: v2(52.32,34.2) 51.93,33.8 49.95,33.8 47.74,31.6 47.74,26.29 43.16,21.71 42.02,21.71 40.68,20.37 40.68,18.09 v2(41.08,17.69)
DDR_DQ24: length 13.5
  TOP w0.127: U1.AB2 v2(49.92,29.4) ; U20.B3 v2(52.21,19.29)
  BOTTOM w0.127: v2(52.21,19.29) 52.83,19.29 53.35,19.81 53.35,21.33 50.33,24.35 50.33,28.99 v2(49.92,29.4)
DDR_DQ25: length 15.6
  TOP w0.127: U20.C7 55.81,18.34 56.19,18.72 56.19,19.96 55.69,20.47 55,20.47 51.34,24.13 51.34,28.72 52.36,29.74 52.36,30.02 52.72,30.38 52.72,30.6
DDR_DQ26: length 13.4
  TOP w0.127: U20.C2 v2(52.21,18.49) ; U1.AC2 v2(49.92,28.6)
  BOTTOM w0.127: v2(49.92,28.6) 49.92,24.12 52.92,21.13 52.92,20.04 52.59,19.71 52.05,19.71 51.82,19.47 51.82,18.88 v2(52.21,18.49)
DDR_DQ27: length 15.3
  TOP w0.127: U20.C8 57.01,18.48 57.01,20.42 56.32,21.1 54.97,21.1 51.72,24.35 51.72,28.52 52.72,29.52 52.72,29.8
DDR_DQ28: length 16.5
  TOP w0.127: v2(53.64,16.91) 53.23,16.49 U20.E3 ; U1.AA4 v2(51.52,30.2)
  BOTTOM w0.127: v2(51.52,30.2) 51.65,30.07 51.65,24.28 54.26,21.66 54.26,17.53 v2(53.64,16.91)
DDR_DQ29: length 16.5
  TOP w0.127: U1.AC6 53.52,25.3 58.96,19.86 58.96,17.45 58.39,16.87 57.22,16.87 56.83,16.49 U20.E8
DDR_DQ30: length 14.9
  TOP w0.127: v2(50.72,29.4) U1.AB3 51.12,29.8 ; U20.D2 v2(52.21,17.69)
  BOTTOM w0.127: v2(52.21,17.69) 52.21,17.71 52.61,18.11 52.61,18.61 52.87,18.87 53.15,18.87 53.76,19.48 53.76,21.53 51.22,24.07 51.22,28.9 v2(50.72,29.4)
DDR_DQ31: length 18.6
  TOP w0.127: U1.AA6 53.12,30.2 53.12,25.12 58.56,19.68 58.56,17.95 58.3,17.69 57.28,17.69 57.01,17.42 57.01,17.12 56.77,16.87 56.33,16.87 55.95,16.49 U20.E7
DDR_DQS0N: length 12.2
  TOP w0.114: U3.D3 40.83,45.99 41,45.82 41,45.54 47.87,38.67 48.92,38.67 48.92,38.67 49.45,38.67 U1.L1
DDR_DQS0P: length 12.3
  TOP w0.114: U1.L2 50.1,38.6 49.77,38.93 48.65,38.93 47.99,38.93 41.27,45.65 41.27,45.95 U3.C3
DDR_DQS1N: length 16
  TOP w0.114: U6.D3 40.6,31.28 40.6,30.58 41.02,30.16 42.66,30.16 44.01,31.51 44.01,33.84 47.55,37.38 50.71,37.38 51.12,37.8
DDR_DQS1P: length 15.9
  TOP w0.114: U1.M2 50.17,37.65 49.81,37.65 49.69,37.77 49.69,37.9 49.58,38.02 49.35,38.02 49.24,37.9 49.24,37.77 49.12,37.65 48.89,37.65 48.78,37.77 48.78,37.9 48.67,38.02 48.44,38.02 48.32,37.9 48.32,37.77 48.21,37.65 47.44,37.65 43.75,33.96 43.75,31.62 42.55,30.42 41.13,30.42 40.86,30.69 40.86,31.17 41.05,31.36 U6.C3
DDR_DQS2N: length 23.7
  TOP w0.114: U1.V2 50.19,33.13 49.95,33.13 49.83,33.02 49.83,32.8 49.72,32.69 49.49,32.69 49.37,32.8 49.37,33.02 49.26,33.13 48.61,33.13 47.42,31.94 47.42,26.78 43.29,22.65 42.3,22.65 39.18,19.53 39.18,18.82 38.05,17.69 37.63,17.69 37.48,17.54 U21.D3
DDR_DQS2P: length 23.7
  TOP w0.114: 51.12,33 U1.V3 50.92,33 50.51,33.4 48.5,33.4 47.15,32.05 47.15,26.89 43.16,22.91 42.18,22.91 38.91,19.64 38.91,18.93 37.93,17.95 37.61,17.95 U21.C3
DDR_DQS3N: length 19.8
  TOP w0.114: U1.W2 50.12,32.2 49.72,31.8 49.53,31.8 49.53,31.81 48.43,31.81 48.17,31.55 48.17,27.86 50.07,25.95 50.07,23.57 53.81,19.83 53.81,17.98 53.32,17.5 52.82,17.5 U20.D3
DDR_DQS3P: length 19.7
  TOP w0.114: U20.C3 52.61,17.94 52.79,17.76 53.21,17.76 53.54,18.09 53.54,19.72 49.81,23.46 49.81,25.84 47.9,27.75 47.9,31.66 48.32,32.08 48.57,32.08 48.68,32.18 48.68,32.42 48.79,32.53 48.97,32.53 49.08,32.42 49.08,32.18 49.18,32.08 49.4,32.08 U1.W1
DDR_ODT: length 118
  TOP w0.127: U6.G1 38.12,33.24 v2(38.52,33.64) ; U20.G1 50.73,14.89 v2(50.33,15.29) 50.1,15.29 46.9,12.09 46.9,10.41 45.63,9.14 v2(45.63,6.52) ; v2(36.98,49.38) 38.12,48.25 U3.G1 ; U21.G1 v2(35.48,15.29) ; U1.AB15 v2(61.12,29.4)
  BOTTOM w0.127: v2(50.33,15.29) 50.2,15.16 48.9,15.16 48.78,15.29 46.49,15.29 46.01,15.77 40.01,15.77 39.25,15 38.2,15 37.69,14.49 35.98,14.49 35.48,14.99 v2(35.48,15.29) 32.49,15.29 31.17,16.61 31.17,20.64 32.67,22.14 36.26,22.14 38.76,24.65 38.76,26.57 38.45,26.88 38.45,28.05 38.31,28.19 38.31,30.55 37.78,31.09 37.78,32.74 38.52,33.47 v2(38.52,33.64) 38.54,33.67 38.54,40.72 38.54,40.72 38.54,43.47 38.1,43.91 38.1,45.27 37.96,45.41 37.96,45.84 37.23,46.57 37.23,48.59 36.98,48.84 v2(36.98,49.38) 36.98,50.72 36.88,50.82 RN5.3 ; v2(61.12,29.4) 60.69,28.97 60.69,27.85 60.55,27.71 60.55,24.34 63.29,21.59 63.29,11.27 59.08,7.06 55.84,7.06 55.44,6.66 53.61,6.66 52.74,5.79 46.36,5.79 v2(45.63,6.52)
DDR_PLL: length 9.7
  TOP w0.254: v2(57.92,35) 57.91,35 56.59,35 55.55,35 55.01,35.55 v2(55.01,36.47)
  TOP w0.305: v2(55.01,36.47) 55.12,36.58 55.12,37 ; U1.T12 v2(57.92,35)
  BOTTOM w0.381: C270.1 57.92,35 v2(57.92,35) ; LB7.1 54.53,38.61 54.53,38.07 54.86,37.74 C11.1 54.86,36.62 v2(55.01,36.47) 55.01,36.15 C264.1
DDR_RASN: length 122.8
  TOP w0.127: v2(44.87,6.52) 44.87,9.19 46.26,10.59 46.26,12.11 49.89,15.74 50.46,15.74 50.92,15.29 v2(52.21,15.29) U20.F3 ; U1.AB16 v2(61.12,30.2) ; v2(37.08,15.29) U21.F3 ; v2(38.52,31.76) U6.F3 ; v2(38.52,46.39) U3.F3
  BOTTOM w0.127: v2(44.87,6.52) 45.98,5.41 52.92,5.41 53.78,6.27 55.79,6.27 55.89,6.17 59.27,6.17 64.05,10.95 64.05,21.91 61.36,24.6 61.36,27.74 61.58,27.96 61.58,29.74 v2(61.12,30.2) ; RN5.1 37.9,50.9 38.52,50.29 38.52,47.93 38.01,47.42 38.01,46.9 v2(38.52,46.39) 38.84,46.06 38.84,43.89 39.12,43.61 39.12,39.19 39.28,39.04 39.28,32.56 38.52,31.8 v2(38.52,31.76) 38.94,31.34 38.94,30.79 38.87,30.72 38.87,28.72 39.4,28.18 39.4,27.48 40.04,26.84 40.04,24.66 36.76,21.38 33.18,21.38 31.93,20.13 31.93,16.97 32.83,16.07 36.29,16.07 v2(37.08,15.29) 37.37,15.59 37.49,15.71 39.17,15.71 39.77,16.3 50.83,16.3 51.85,15.29 v2(52.21,15.29)
DDR_RESETN: length 112.4
  TOP w0.127: C301.1 52.23,6.78 52,7.01 v2(51.98,7.01) 51.98,9.93 U20.N2 51.67,9.95 51.67,9.67 49.69,7.69 49.69,5.76 47.98,4.05 43.65,4.05 42.33,5.38 37.91,5.38 C300.1 36.86,6.42 36.86,9.9 U21.N2 36.56,9.97 36.56,9.67 36.2,9.32 34.81,9.32 33.62,10.5 33.62,11.05 32.48,12.19 32.48,12.83 30.31,15 30.31,22.75 28.99,24.07 28.99,30.22 30.66,31.89 33.05,31.89 U6.N2 33.11,32.36 32.72,32.36 32.28,32.8 32.28,34.17 30.03,36.42 30.03,42.37 29.22,43.18 v1(29.22,43.36) 28.96,43.62 28.96,45 30.34,46.38 32.9,46.38 U3.N2 ; 59.12,29.8 v2(59.52,29.4)
  BOTTOM w0.127: C298.1 29.27,43.31 v1(29.22,43.36) 29.27,43.41 R46.1 C299.1 ; v2(51.98,7.01) 52,7.03 52.01,7.03 52.87,7.89 55.07,7.89 55.38,8.2 58.61,8.2 62.15,11.74 62.15,21.12 59.25,24.02 59.25,28.24 59.52,28.51 v2(59.52,29.4)
DDR_VREF_A: length 13.5
  TOP w0.203: U3.J8 36.9,42.37 37.54,42.37 37.7,42.54 v2(37.7,43.3) 37.7,44.06 39.3,45.66 39.3,47.18 U3.E1
  TOP w0.305: U3.E1 v2(40.92,48.79)
  BOTTOM w0.254: C49.1 37.17,43.84 v2(37.7,43.3)
  BOTTOM w0.381: v2(40.92,48.79) 40.94,48.81 R124.1 ; R123.2 C210.2 R124.1 ; R124.1 C211.1
DDR_VREF_B: length 14.2
  TOP w0.203: U6.E1 39.3,32.55 39.3,31.03 38.64,30.37 38.41,30.37 37.65,29.62 v2(37.65,28.67) 37.7,28.63 37.7,28 37.44,27.74 36.9,27.74 U6.J8
  TOP w0.305: U6.E1 39.72,32.96 39.72,33.67 v2(40.52,34.47)
  BOTTOM w0.254: C66.1 37.22,29.1 v2(37.65,28.67)
  BOTTOM w0.381: R103.1 40.9,35.15 40.52,34.76 v2(40.52,34.47) ; R103.1 R84.2 C202.2 ; R103.1 41.16,35.43 40.78,35.81 C203.1
DDR_VREF_C: length 14.5
  TOP w0.203: U21.J8 41.19,13.58 41.19,13.58 41.06,13.71 41.06,14.25 40.83,14.47 40.83,14.47 40.83,14.47 v2(40.14,14.47) 39.41,14.47 37.8,16.08 36.29,16.08 U21.E1
  TOP w0.305: U21.E1 34.91,16.49 v2(34.13,17.27)
  BOTTOM w0.254: v2(40.14,14.47) 39.48,13.81 C86.1
  BOTTOM w0.381: R139.1 C235.1 33.92,19.12 34.65,19.86 C234.2 ; R139.1 33.92,17.49 v2(34.13,17.27) ; R139.1 33.28,17.98 33.21,18.05 R133.2
DDR_VREF_D: length 14.3
  TOP w0.203: U20.J8 56.21,13.69 56.21,14.32 56.06,14.47 v2(55.25,14.47) 54.44,14.47 52.83,16.09 51.66,16.09 51.26,16.49 U20.E1
  TOP w0.305: v2(49.5,17.29) 50.3,16.49 U20.E1
  BOTTOM w0.254: v2(55.25,14.47) 54.75,14.47 54.49,14.22 C87.1
  BOTTOM w0.381: v2(49.5,17.29) 49.21,17.29 48.88,17.62 C225.1 R130.1 R129.2 C224.2
DDR_VTT: length 16
  BOTTOM w0.254: RN3.5 28,48.59 ; RN3.8 28,50.11 ; RN4.5 31.61,53 ; RN5.7 37.39,52.99 ; RN5.5 36.37,52.99 ; RN4.8 33.13,53 ; 28.11,46.16 RN6.5 ; RN1.5 38.79,52.99 ; RN7.7 35,52.99 ; RN7.5 33.99,52.99 ; RN5.8 37.9,52.99 ; RN4.7 32.62,53 ; RN5.6 36.88,52.99 ; RN6.7 27.99,47.17 ; RN3.7 28,49.6 ; 28.11,46.67 RN6.6 ; RN7.8 35.51,52.99 ; RN6.8 27.99,47.68 ; RN1.6 39.3,52.99 ; RN3.6 28,49.09 ; RN7.6 34.49,52.99 ; RN4.6 32.11,53
  vias: v1(40.93,52.24) v1(40.93,51.48)
DDR_WEN: length 114.1
  TOP w0.127: v2(58.72,31) U1.Y13 59.12,31.4 ; v2(56.13,8.6) 55.73,9.01 55.73,9.25 55.19,9.79 55.19,12.07 53.17,14.09 U20.H3 52.16,13.63 51.56,13.63 51.36,13.43 51.36,13.15 51.09,12.88 49.98,12.88 48.36,11.26 48.36,10.15 47.33,9.12 47.33,6.83 46.57,6.07 44.69,6.07 41.59,9.16 40.87,9.16 40.29,9.74 40.29,12.15 38.35,14.09 U21.H3 37.02,13.63 36.53,13.63 36.25,13.35 36.25,13.1 36.05,12.9 35.09,12.9 34.83,13.15 34.83,13.46 34.27,14.02 34.27,15.59 32.24,17.62 32.24,24.05 31.78,24.51 31.78,26.23 32.11,26.56 32.11,27.88 33.03,28.8 35.26,28.8 36.58,30.12 36.81,30.12 37.32,30.62 U6.H3 36.91,31.76 36.91,32.36 36.69,32.58 36.38,32.58 36.11,32.85 36.11,34.4 32.01,38.51 32.01,42.39 33.06,43.44 35.05,43.44 36.48,44.88 36.87,44.88 37.32,45.32 U3.H3 36.91,46.39 36.91,46.99 36.71,47.19 36.36,47.19 36.13,47.42 36.13,47.99 36.12,47.99 36.12,48.32 36.13,48.33 36.13,49.7 36.43,50.01 36.43,51.28 R17.1
  BOTTOM w0.127: v2(56.13,8.6) 58.47,8.6 61.77,11.9 61.77,20.94 58.85,23.86 58.85,28.45 59.09,28.69 59.09,30.63 v2(58.72,31)
FE_1V1: length 1.3
  TOP w0.305: U1.G10 v2(56.32,41.4)
  BOTTOM w0.381: C248.1 56.17,41.25 v2(56.32,41.4)
FE_3V3: length 0.6
  TOP w0.305: v2(52.32,43.8) U1.E5 52.72,43.4
HDMI_TX0N: length 42.9
  TOP w0.114: U1.D16 61.86,44.54 61.86,47.69 59.48,50.07 59.48,50.87 50.58,59.78 50.58,63.56 46.54,67.6 46.54,73.52 46.65,73.64 U24.2 U24.9 46.65,75.64 46.54,75.76 46.54,76.2 47.29,76.95 47.29,77.74 47.72,78.17 J26.9
HDMI_TX0P: length 42.9
  TOP w0.114: U1.C16 61.6,45.07 61.6,46.4 61.44,46.56 61.44,46.86 61.6,47.02 61.6,47.58 61.49,47.69 61.33,47.69 61.25,47.61 61.09,47.61 60.93,47.78 60.93,47.94 61,48.01 61,48.17 60.84,48.33 60.68,48.33 60.61,48.26 60.44,48.26 60.28,48.42 60.28,48.58 60.36,48.66 60.36,48.82 59.22,49.96 59.22,50.76 50.31,59.67 50.31,63.45 46.27,67.49 46.27,73.51 46.15,73.63 U24.1 U24.10 46.15,75.62 46.27,75.74 46.27,76.31 47.02,77.06 47.02,77.8 46.72,78.11 J26.7
HDMI_TX1N: length 42
  TOP w0.114: U1.B15 61.07,46.15 61.07,46.57 61.07,47.08 58.35,49.8 58.35,49.97 58.35,50.15 57.75,50.75 57.41,50.75 49.53,58.63 49.53,63.19 44.87,67.85 44.87,73.58 44.98,73.7 U23.5 U23.6 44.98,75.69 44.86,75.81 44.86,76.09 45.75,76.98 45.75,77.76 46.22,78.23 J26.6
HDMI_TX1P: length 42
  TOP w0.114: J26.4 45.22,78.08 45.49,77.82 45.49,77.09 44.6,76.2 44.6,75.81 44.48,75.7 U23.7 U23.4 44.48,73.69 44.6,73.57 44.6,67.74 49.26,63.08 49.26,58.52 57.3,50.48 57.64,50.48 58.08,50.04 58.08,49.69 58.79,48.99 58.79,48.83 58.71,48.76 58.71,48.6 58.87,48.43 59.04,48.43 59.11,48.51 59.27,48.51 59.43,48.34 59.43,48.18 59.36,48.11 59.36,47.95 59.52,47.79 59.68,47.79 59.76,47.86 59.92,47.86 60.08,47.7 60.08,47.54 60.08,47.36 60.22,47.21 60.4,47.21 60.56,47.21 60.8,46.97 60.8,46.68 U1.A15
HDMI_TX2N: length 42.9
  TOP w0.114: J26.3 44.72,78.12 44.38,77.79 44.38,77.3 43.36,76.28 43.36,75.73 43.48,75.61 U23.9 U23.2 43.48,73.57 43.35,73.44 43.35,67.76 48.29,62.82 48.29,58.46 60.28,46.47 60.28,45.36 U1.C14
HDMI_TX2P: length 42.8
  TOP w0.114: U1.B14 60.02,45.89 60.02,46.36 59.8,46.58 59.64,46.58 59.56,46.5 59.4,46.5 59.24,46.66 59.24,46.82 59.32,46.9 59.32,47.06 59.16,47.22 59,47.22 58.92,47.14 58.75,47.14 58.59,47.3 58.59,47.47 58.67,47.55 58.67,47.71 48.03,58.35 48.03,62.71 43.08,67.65 43.08,73.53 42.98,73.64 U23.1 U23.10 42.98,75.62 43.1,75.74 43.1,76.39 44.12,77.41 44.12,77.75 43.72,78.14 J26.1
HDMI_TX_1V1: length 1.1
  TOP w0.305: U1.G14 59.92,41.8 v2(60.32,41.4) U1.G15
HDMI_TX_3V3: length 0.6
  TOP w0.381: U1.E15 v2(60.32,43.8)
HDMI_TX_CEC: length 42.3
  TOP w0.127: J26.13 49.72,75.89 48.8,74.98 48.8,72.94 49.28,72.47 50.31,72.47 U4.3 50.31,71.89 49.92,71.5 R268.2 49.92,66.63 52.36,64.2 52.36,61.22 61.05,52.53 61.05,52.1 61.63,51.52 61.63,50.16 63.03,48.76 63.03,45.64 63.12,45.54 63.12,45
HDMI_TX_HOTPLUG: length 42.5
  TOP w0.127: J26.19 52.72,78.47 54.42,76.77 54.42,76.46 55.66,75.22 55.66,73.71 54.43,72.47 U4.4 52.81,71.91 52.84,71.89 R8.2 C149.1 52.84,69.41 53.76,68.5 53.76,61.11 61.89,52.97 61.89,52.5 62.55,51.85 62.55,50.39 63.79,49.14 63.79,47.42 64.32,46.88 64.32,46.48 63.92,46.08 63.92,45.8 U1.B19
HDMI_TX_SCL: length 42.7
  TOP w0.127: J26.15 50.72,76.87 51.19,76.4 R186.1 50.69,75.73 50.31,75.35 U4.1 51.05,74.37 51.39,74.03 51.39,68.46 52.74,67.12 52.74,61.25 61.33,52.65 61.33,52.22 61.91,51.65 61.91,50.26 63.28,48.89 63.28,45.92 63.51,45.69 63.51,44.59 63.12,44.2
HDMI_TX_SDA: length 40.1
  TOP w0.127: U1.A19 63.53,46.98 63.53,49.02 62.23,50.32 62.23,51.73 61.61,52.35 61.61,52.81 53.12,61.3 53.12,67.25 51.75,68.62 51.75,74.05 52.07,74.37 U4.6 52.81,75.08 52.97,75.23 R187.1 52.97,76.34 51.22,78.09 J26.16
HDMI_TXCN: length 42.4
  TOP w0.114: U1.B17 62.67,46.15 62.67,48.28 60.47,50.48 60.47,51.41 60.11,51.77 60.11,51.94 60.24,52.07 60.24,52.45 59.76,52.93 59.38,52.93 59.24,52.8 59.08,52.8 58.76,53.12 58.76,53.28 58.89,53.42 58.89,53.8 58.41,54.28 58.03,54.28 57.9,54.15 57.73,54.15 51.58,60.3 51.58,64.08 48.05,67.61 48.05,73.52 48.15,73.62 U24.5 U24.6 48.15,75.64 48.04,75.75 48.04,76.23 48.84,77.04 48.84,77.85 49.22,78.23 J26.12
HDMI_TXCP: length 42.4
  TOP w0.114: U1.A17 62.4,46.68 62.4,48.17 62.18,48.39 62.01,48.39 61.97,48.35 61.81,48.35 61.65,48.51 61.65,48.68 61.69,48.72 61.69,48.88 61.53,49.04 61.37,49.04 61.33,49 61.16,49 61,49.16 61,49.32 61.04,49.36 61.04,49.53 60.88,49.69 60.72,49.69 60.68,49.65 60.52,49.65 60.36,49.81 60.36,49.97 60.4,50.01 60.4,50.17 60.2,50.37 60.2,51.3 59.84,51.66 59.84,52.05 59.97,52.18 59.97,52.34 59.65,52.67 59.49,52.67 59.35,52.53 58.97,52.53 58.49,53.01 58.49,53.39 58.63,53.53 58.63,53.69 58.3,54.01 58.14,54.01 58.01,53.88 57.62,53.88 51.31,60.19 51.31,63.97 47.79,67.5 47.79,73.52 47.65,73.65 U24.4 U24.7 47.65,75.67 47.77,75.79 47.77,76.34 48.58,77.15 48.58,77.85 48.22,78.21 J26.10
IR_IN: length 33.5
  TOP w0.127: v1(65.87,25.62) 65.69,25.8 65.69,29.84 65.18,30.36 65.18,31.05 U1.Y21 ; D3.1 70.09,4.82 70.14,4.87 R140.1 69.66,5.99 69.35,6.29 69.35,8.93 69.74,9.32 69.74,10.74 70.07,11.07 v1(70.4,11.07)
  BOTTOM w0.127: v1(70.4,11.07) 70.4,11.76 71.21,12.57 71.21,13.69 68.93,15.98 68.93,21.73 65.87,24.79 v1(65.87,25.62)
LED0_BASE: length 45.8
  TOP w0.127: U1.B2 49.93,45.41 49.28,45.41 48.9,45.79 48.9,47.39 49.56,48.05 49.56,50.73 46.15,54.15 44.99,54.15 41.56,57.58 28.24,57.58 26.26,59.56 26.26,60.95 24.21,62.99 20.78,62.99 20.1,63.67 20.1,64.76 R26.2 R67.2
LED0_LINK_ACT: length 31.3
  TOP w0.127: v1(37.75,58.09) 41.69,58.09 45.12,54.66 46.02,54.66 49.95,50.73 49.95,47.98 49.16,47.19 49.16,46.16 U1.B1 ; R30.2 R79.2 v1(37.75,66.18)
  BOTTOM w0.127: v1(37.75,66.18) 38.7,65.23 38.7,59.04 v1(37.75,58.09)
LED_GREEN: length 29.1
  TOP w0.127: v1(66.73,25.52) 65.95,26.31 65.95,29.42 U1.AB22
  BOTTOM w0.127: R3.2 66.45,9.53 67.08,9.53 67.28,9.72 R48.1 ; R48.1 67.65,9.28 67.79,9.14 69.18,9.14 69.92,9.88 70.55,9.88 70.9,10.23 70.9,11.83 71.6,12.52 71.6,13.77 69.31,16.06 69.31,21.85 66.73,24.43 v1(66.73,25.52) ; R48.1 R22.1
LED_RED: length 27.3
  TOP w0.127: U1.AC22 66.32,28.63 66.28,28.59 66.28,26.7 67.47,25.51 v1(67.47,25.07)
  BOTTOM w0.127: v1(67.47,25.07) 67.47,24.15 69.69,21.93 69.69,16.13 71.98,13.84 71.98,12.47 71.18,11.67 71.18,10 70.78,9.6 70.15,9.6 69,8.45 R60.2 R39.1 R31.1
MOS_CTRL: length 135.9
  TOP w0.127: R118.1 74.96,17.66 v1(76.29,16.33) ; v2(44.23,48.48) 44.23,49.72 40.94,53.01 33.31,53.01 31.84,51.54 31.84,48.64 27.65,44.45 v1(27.65,44.09)
  BOTTOM w0.127: v1(27.65,44.09) 27.65,37.7 27.97,37.38 27.97,27.73 23.78,23.54 23.78,12.13 21.68,10.03 21.68,7.49 22.32,6.86 26.51,6.86 30.32,3.05 59.28,3.05 61.94,5.71 73.37,5.71 74.58,6.92 Q13.1 74.58,12.39 C6.2 76.11,13.91 76.11,16.14 v1(76.29,16.33) 76.6,16.33 77.39,15.54 Q14.1 ; v2(44.23,48.48) Q8.1
MUTE_CTRL: length 31.6
  TOP w0.127: R90.1 55.66,70.17 54.14,68.65 54.14,61.13 62.17,53.1 62.17,52.69 64.8,50.06 64.8,47.42 65.08,47.14 65.08,46.43 64.86,46.2 64.59,46.2 64.31,45.93 64.31,45.39 U1.C19
NF_ALE_EMMC_PWREN: length 33.4
  TOP w0.127: U19.17 84.01,47.4 83.38,48.03 80.26,48.03 79.98,47.75 79.98,45.47 81.25,44.2 81.25,37.93 79.52,36.2 68.25,36.2 68.13,36.09 66.23,36.09 65.72,36.6 65.12,36.6 U1.N20
NF_CLE: length 33.1
  TOP w0.127: U19.16 84.51,47.41 83.61,48.31 80.13,48.31 79.7,47.88 79.7,45.24 80.87,44.07 80.87,37.93 79.39,36.46 68.09,36.46 67.98,36.34 66.4,36.34 65.75,37 U1.N21
NF_CSN0_EMMC_CMD: length 47.7
  TOP w0.127: v2(85.35,40.89) 87.54,43.08 87.54,44.32 88.01,44.8 U19.9 88.01,47.34 87.72,47.62 84.8,47.62 83.84,48.59 80,48.59 79.42,48.01 79.42,45.01 80.49,43.94 80.49,37.94 79.26,36.71 67.89,36.71 67.78,36.6 66.72,36.6 U1.N22
  TOP w0.254: U22.W5 87.51,38.66 v2(87.22,38.36)
  BOTTOM w0.127: v2(87.22,38.36) 86.92,38.06 86.92,38.06 86.78,37.92 86.25,37.92 85.86,38.32 85.86,39.84 85.57,40.12 R212.2 85.22,40.76 85.35,40.89 v2(85.35,40.89)
NF_DQ0_EMMC_D0: length 36.4
  TOP w0.127: U22.H3 88.51,32.48 v2(88.74,32.26) ; v2(84.93,30.61) 84.55,30.61 82.51,28.57 U19.29 82.51,25.95 82.39,25.83 80.29,25.83 79.62,26.49 79.62,33.21 77.81,35.02 68.28,35.02 67.91,35.4 67.12,35.4
  BOTTOM w0.127: v2(88.74,32.26) 88.61,32.38 86.2,32.38 84.97,31.15 84.97,30.64 v2(84.93,30.61) 84.57,30.25 R189.2
NF_DQ1_EMMC_D1: length 36.3
  TOP w0.102: 68.16,34.77 67.87,35.06 66.66,35.06 U1.R22
  TOP w0.127: 68.16,34.77 77.63,34.77 79.29,33.11 79.29,26.44 80.16,25.57 82.58,25.57 83.01,26 U19.30 v1(83.01,28.07) ; v2(87.6,31.5) 88.01,31.91 U22.H4
  BOTTOM w0.127: v1(83.01,28.07) 82.92,28.16 R12.2 83.91,28.83 85.57,30.48 85.57,31.14 86.43,32 87.09,32 v2(87.6,31.5)
NF_DQ2_EMMC_D2: length 36.9
  TOP w0.102: U1.R21 66.09,34.83 67.72,34.83 68.06,34.49
  TOP w0.127: v2(86.58,31.5) 86.58,31.75 87.51,32.68 U22.H5 ; v2(85.57,29.21) 84.68,29.21 83.51,28.05 U19.31 83.51,25.46 R29.2 83.12,24.81 82.86,24.56 80.81,24.56 78.96,26.4 78.96,32.95 77.43,34.49 68.06,34.49
  BOTTOM w0.127: v2(86.58,31.5) 86.07,30.99 86.07,29.72 v2(85.57,29.21)
NF_DQ3_EMMC_D3: length 40.5
  TOP w0.089: U22.J2 88.76,33.62 88.76,33
  TOP w0.102: 67.95,34.23 67.59,34.6 U1.T21
  TOP w0.127: 67.95,34.23 77.25,34.23 78.63,32.85 78.63,26.35 81.44,23.54 82.79,23.54 83.12,23.87 R58.2 84.01,24.95 U19.32 84.01,27.79 84.91,28.68 87.06,28.68 87.6,29.21 87.6,29.97 88.11,30.48 88.61,30.48 89.22,31.09 89.22,32.54 88.76,33
NF_DQ4_EMMC_D4: length 44.7
  TOP w0.089: 88.26,33.01 88.26,33.62 U22.J3
  TOP w0.102: 67.85,33.98 67.46,34.37 66.36,34.37 66.2,34.21 65.11,34.21 U1.T20
  TOP w0.127: v2(88.74,31.24) 88.26,31.72 88.26,33.01 ; 67.85,33.98 77.07,33.98 78.3,32.75 78.3,26.32 81.34,23.29 87.9,23.29 88.51,23.9 U19.41 88.51,28.19 88.11,28.6 88.11,29.34 v2(88.61,29.84)
  BOTTOM w0.127: v2(88.61,29.84) 88.61,31.11 v2(88.74,31.24) 89.84,31.24 R176.2
NF_DQ5_EMMC_D5: length 45.8
  TOP w0.089: U22.J4 87.76,33.62 87.76,33.06
  TOP w0.102: 67.75,33.73 67.34,34.14 66.66,34.14 U1.U22
  TOP w0.127: 67.75,33.73 76.84,33.73 77.97,32.6 77.97,26.29 81.23,23.03 88.15,23.03 89.01,23.9 U19.42 89.01,28.56 v2(88.61,28.96) ; 87.76,33.06 87.76,32.42 87.09,31.75 87.09,31.11 v2(87.6,30.61)
  BOTTOM w0.127: v2(88.61,28.96) 87.6,29.97 v2(87.6,30.61) 87.6,30.73 88.61,31.75 89.75,31.75 R177.2
NF_DQ6_EMMC_D6: length 46.6
  TOP w0.089: U22.J5 87.51,33.77 87.26,33.52 87.26,33.22
  TOP w0.127: 67.12,33.8 67.45,33.47 76.64,33.47 77.64,32.47 77.64,26.2 81.06,22.78 88.41,22.78 89.51,23.89 U19.43 89.51,29.33 v2(89.38,29.46) ; v2(86.58,30.61) 86.07,31.11 86.07,31.75 87.26,32.94 87.26,33.22
  BOTTOM w0.127: v2(86.58,30.61) 86.58,30.23 88.36,28.45 89.12,28.45 89.38,28.7 v2(89.38,29.46) 89.38,29.72 89.67,30.02 90.05,30.02 R188.2
NF_DQ7_EMMC_D7_BOOT_SEL0: length 48.3
  TOP w0.089: U22.J6 86.76,33.62 86.76,32.99 86.52,32.74
  TOP w0.127: v1(90.01,28.07) U19.44 90.01,23.88 88.66,22.53 80.93,22.53 77.31,26.15 77.31,32.37 76.46,33.22 70.39,33.22 R82.1 69.63,33.22 66.1,33.22 U1.U21 ; v2(86.58,29.21) 86.58,29.59 85.69,30.48 85.69,31.92 86.52,32.74
  BOTTOM w0.127: v2(86.58,29.21) 87.09,29.21 88.23,28.07 v1(90.01,28.07) 90.05,28.1 R202.2
NF_RDY0_EMMC_RST: length 53.4
  TOP w0.127: U1.M21 65.93,37.38 67.53,37.38 67.65,37.27 68.2,37.27 68.65,37.72 78.96,37.72 79.72,38.48 79.72,43.69 78.86,44.55 78.86,48.26 79.75,49.15 84.3,49.15 85.06,48.39 87.98,48.39 89.01,47.35 U19.7 89.01,44.91 91.54,42.39 91.54,38.22 91.11,37.79 v2(90.65,37.33)
  TOP w0.254: v2(88,35.99) 88,35.99 88,37.43 87.56,37.87 U22.U5
  BOTTOM w0.127: v2(90.65,37.33) R203.2 C115.1 88.83,37.33 88,36.5 88,36.41 88,36.41 v2(88,35.99)
NF_REN_EMMC_CLK: length 42.5
  TOP w0.127: v2(86.15,40.89) 86.15,41.31 87.64,42.8 88.15,42.8 88.51,43.16 U19.8 88.51,47.34 87.85,48.01 84.93,48.01 84.07,48.87 79.88,48.87 79.14,48.13 79.14,44.78 80.1,43.81 80.1,38.18 79.14,37.21 R65.1
  TOP w0.254: v2(86.47,38.37) 86.54,38.37 87.01,38.84 U22.W6
  BOTTOM w0.127: v2(86.47,38.37) 86.17,38.67 86.17,38.67 86.16,38.68 86.16,40.47 86.15,40.47 v2(86.15,40.89)
NF_WEN_EMMC_DET: length 27.6
  TOP w0.127: U1.P21 65.96,35.76 68.18,35.76 v1(68.33,35.61) 68.66,35.94 79.74,35.94 81.63,37.83 81.63,41.86 83.51,43.74 U19.18
  BOTTOM w0.127: v1(68.33,35.61) 68.21,35.48 R56.2
NF_WP: length 5.2
  TOP w0.254: v2(82.66,43.58) 83.01,43.94 U19.19
  BOTTOM w0.381: R215.2 R89.1 82.08,43 v2(82.66,43.58)
PWR_OFF/ON: length 2.9
  TOP w0.127: 67.12,40.2 67.69,40.2 68.16,40.67 R51.1 R44.1
RECOVERY: length 51.6
  TOP w0.127: U1.J22 66.32,40.41 65.95,40.79 65.95,41.55 67.62,43.23 67.62,45.03 67.9,45.31 67.9,47.47 66.25,49.12 66.25,50.95 63.98,53.22 63.98,60.69 66.66,63.37 68.8,63.37 71.28,65.85 71.28,75.14 R47.2 C42.2 70.61,83.85 S1.2
RF0: length 8.6
  TOP w0.127: L1.2 C64.1 17.48,11.83 arc(17.77,11.89) 18,12.05 20.17,14.22 arc(20.83,15.2) 21.07,16.37 U7.3
RF1: length 4
  TOP w0.127: L7.2 C50.1 17.64,15.13 arc(17.97,15.64) 18.09,16.24 U2.7
RFF0: length 3
  TOP w0.127: J5.1 13.73,10.84 arc(13.98,10.89) 14.19,11.03 arc(14.34,11.24) 14.39,11.49 C61.1 L1.1
RFF1: length 3
  TOP w0.127: J4.1 13.72,15.68 arc(13.97,15.63) 14.19,15.48 arc(14.33,15.27) 14.39,15.01 C60.1 L7.1
RX+_PHY0: length 35.1
  TOP w0.114: 52.72,44.2 52.35,44.57 52.35,47.85 52.62,48.12 52.93,48.12 53.04,48.23 53.04,48.69 52.93,48.8 52.62,48.8 52.35,49.07 52.35,50.87 43.41,59.81 33.72,59.81 33.6,59.69 U8.3 U8.6 31.62,59.69 31.5,59.81 30.45,59.81 29.81,60.45 29.81,60.81 R63.1
RX-_PHY0: length 35.1
  TOP w0.114: R64.1 30.19,61.06 30.08,60.95 30.08,60.56 30.56,60.08 31.5,60.08 31.62,60.2 U8.5 U8.4 33.6,60.2 33.72,60.08 43.52,60.08 46.38,57.21 52.61,50.98 52.61,49.18 52.73,49.07 53.04,49.07 53.31,48.8 53.31,48.12 53.04,47.85 52.73,47.85 52.61,47.73 52.61,46.16 52.73,46.04 52.94,46.04 53.05,45.93 53.05,45.7 52.94,45.59 52.73,45.59 52.61,45.47 52.61,45.11 52.72,45
SDIO0_CARD_DETECT: length 47.4
  TOP w0.127: U1.F1 48.54,42.6 45.12,46.02 45.12,49.59 40.94,53.77 26.32,53.77 24.57,55.52 v1(21.83,55.52) ; J21.9 v1(15.82,61.78)
  BOTTOM w0.127: v1(21.83,55.52) 21.91,55.6 R155.2 21.14,56.23 20.94,56.43 17.94,56.43 17.74,56.64 17.74,59.86 v1(15.82,61.78)
SDIO0_CCLK_OUT: length 39.9
  TOP w0.127: J21.5 12.77,56.54 12.94,56.71 16.67,56.71 17.92,57.96 25.94,57.96 27.47,56.43 40.54,56.43 46.55,50.42 46.83,50.42 47.41,49.84 R5.1
SDIO0_CCMD: length 49.1
  TOP w0.127: J21.3 12.76,54.34 v1(13.12,53.98) 14.78,53.98 18.38,57.58 25.69,57.58 27.21,56.05 40.51,56.05 46.77,49.79 46.77,45.74 48.7,43.81 49.91,43.81 U1.E2
  BOTTOM w0.127: R153.2 13.13,53.97 v1(13.12,53.98)
SDIO0_CDATA0: length 48.7
  TOP w0.127: J21.7 v1(13.14,58.74) 13.5,59.1 17.18,59.1 17.94,58.34 26.2,58.34 27.72,56.82 40.56,56.82 46.58,50.8 46.91,50.8 47.91,49.79 47.91,45.44 49.01,44.34 50.73,44.34 50.88,44.2 U1.D3 51.12,44.2
  BOTTOM w0.127: R152.2 13.22,58.82 v1(13.14,58.74)
SDIO0_CDATA1: length 49
  TOP w0.127: J21.8 v1(13.14,59.84) 13.5,59.48 17.43,59.48 18.2,58.72 26.45,58.72 27.97,57.2 40.69,57.2 45.38,52.51 46.39,52.51 47.21,51.69 47.21,51.44 47.93,50.72 48.31,50.72 48.62,50.4 48.62,49.02 48.27,48.66 48.27,45.54 49.21,44.6 49.92,44.6 U1.C2
  BOTTOM w0.127: v1(13.14,59.84) 13.85,59.84 R151.2
SDIO0_CDATA2: length 50.7
  TOP w0.127: J21.1 v1(13.04,52.14) 14.31,50.87 15.93,50.87 17.81,52.75 17.81,54.32 19.67,56.18 24.67,56.18 26.7,54.15 40.94,54.15 45.5,49.59 45.5,46.15 48.62,43.02 49.9,43.02 U1.F2
  BOTTOM w0.127: R156.2 13.5,51.68 v1(13.04,52.14)
SDIO0_CDATA3: length 48.4
  TOP w0.127: U1.E1 48.68,43.4 46.39,45.69 46.39,49.77 40.49,55.67 26.96,55.67 25.43,57.2 18.68,57.2 14.49,53.01 v1(13.11,53.01) 12.87,53.24 J21.2
  BOTTOM w0.127: R154.2 13.29,52.83 v1(13.11,53.01)
SDIO0_CWPR: length 4.2
  TOP w0.127: v2(48.75,47.82) 48.56,47.63 48.56,45.63 49.19,45 U1.C1
  BOTTOM w0.127: R25.2 48.68,47.75 v2(48.75,47.82)
SDIO0_PWREN: length 28.8
  TOP w0.127: R76.1 30.19,52.76 30.21,52.78 R149.1 31.45,53.39 40.94,53.39 44.74,49.59 44.74,45.89 48.4,42.24 50.76,42.24 51.12,42.6
SDIO_3318: length 62.7
  TOP w0.254: v1(15.58,51.35) 15.58,53.13 19.14,56.69 25.18,56.69 27.21,54.66 40.94,54.66 45.93,49.67 v2(45.93,47.29)
  TOP w0.305: 52.72,41.8 v2(53.12,41.4)
  BOTTOM w0.254: v2(45.93,47.29) 45.93,46.48 49.74,42.67 52.51,42.67 53.04,42.13 C22.2
  BOTTOM w0.305: v1(15.58,51.35) 15.1,51.35 R156.1 R154.1 R153.1 14.77,54.45 14.57,54.66 12.89,54.66 12.48,55.06 12.48,57.65 12.97,58.14 14.36,58.14 14.67,58.44 R152.1 R151.1 ; v2(53.12,41.4) 53.04,41.48 C22.2
SPDIF_OUT_BOOT_SEL1: length 2.2
  TOP w0.127: R83.1 64.3,47.54 64.72,47.12 U1.A20
STANDBY_PWROFF: length 174.3
  TOP w0.127: v1(66.96,27.48) 66.61,27.83 66.61,28.55 66.73,28.67 66.73,29.41 67.12,29.8 ; R98.1 73.82,17.56 73.85,17.58 v1(73.85,18.03) ; R35.1 v1(18.32,38.27)
  BOTTOM w0.127: R73.1 73.6,49.43 75.47,47.56 75.47,38.9 78.39,35.98 78.39,24.81 73.85,20.26 v1(73.85,18.03) ; v1(73.85,18.03) 73.85,17.43 74.47,16.81 77.77,16.81 78.2,16.38 78.2,14.71 78.02,14.53 77.4,14.53 77.07,14.2 77.07,8.27 73.5,4.7 62.07,4.7 59.4,2.03 30.07,2.03 26,6.1 21.94,6.1 20.92,7.11 20.92,10.39 22.07,11.54 22.07,21.19 20.74,22.53 17.05,22.53 14,25.57 14,37.26 15.02,38.27 v1(18.32,38.27) ; v1(73.85,18.03) 73.37,18.03 73.06,17.72 R81.1 72.04,18.03 72.04,25.57 71.23,26.39 68.31,26.39 67.22,27.48 v1(66.96,27.48) R88.1
TX+_PHY0: length 34
  TOP w0.114: U1.B4 51.57,46.15 51.57,47.07 50.95,47.69 50.95,50.43 42.58,58.79 33.72,58.79 33.6,58.67 U8.1 U8.8 31.62,58.67 31.5,58.79 28.3,58.79 27.4,59.69 27.4,60.81 R59.1
TX-_PHY0: length 34
  TOP w0.114: U1.A4 51.84,46.68 51.84,47.18 51.22,47.8 51.22,48.15 51.33,48.26 51.54,48.26 51.66,48.38 51.66,48.6 51.54,48.72 51.33,48.72 51.22,48.83 51.22,50.54 42.69,59.06 33.72,59.06 33.6,59.18 U8.2 U8.7 31.62,59.18 31.5,59.06 28.41,59.06 27.67,59.8 27.67,60.95 27.78,61.06 R62.1
UART0_RXD: length 49.1
  TOP w0.127: U1.AA22 66.77,30.15 67.45,30.15 68.46,29.13 68.46,27.63 69.88,26.21 76.23,26.21 80.65,21.79 82.94,21.79 87.77,16.96 87.77,11.45 89.27,9.95 89.27,7.01 87.52,5.25 R136.2 82.48,4.85 82.43,4.79 J18.2
UART0_TXD: length 51.4
  TOP w0.127: v1(83.12,4.54) 87.26,4.54 89.65,6.93 89.65,10.08 88.13,11.6 88.13,17.11 83.12,22.12 80.81,22.12 76.36,26.56 70.04,26.56 68.84,27.76 68.84,29.24 67.49,30.6 67.12,30.6 ; J18.3 81.18,4.02 v1(80.7,4.49) R135.2
  BOTTOM w0.127: v1(80.7,4.49) 83.07,4.49 v1(83.12,4.54)
